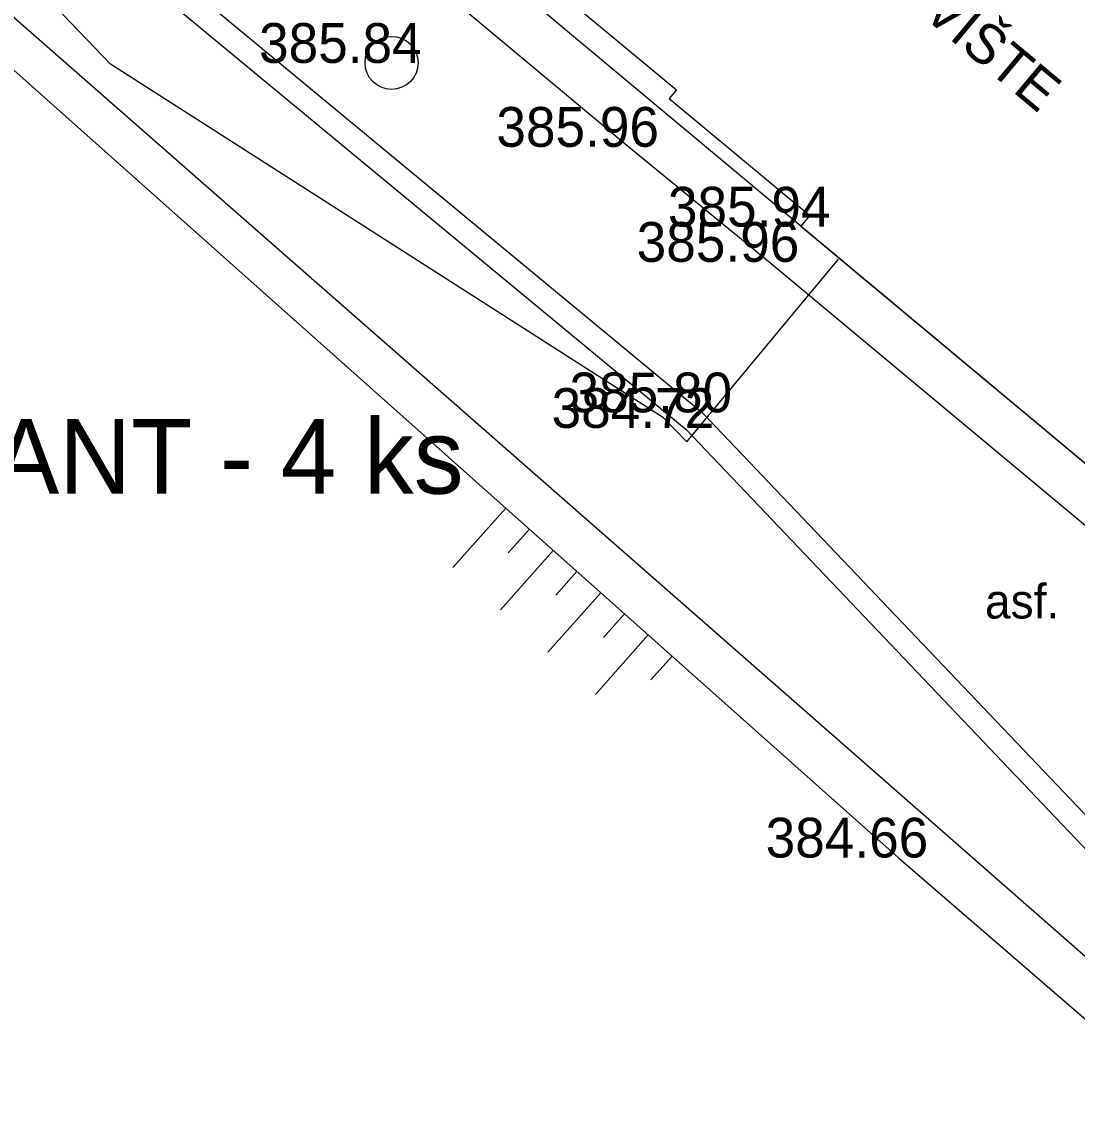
# Model space of a CAD drawing. Extents: x -438233 to -437334, y -1133133 to -1132623.
# Drawn here: x -438124.22 to -438104.32, y -1133015.76 to -1132995.04 of the extents above; entities that cross this region are included whole.
import ezdxf

# ---------------------------------------------------------------- set-up
doc = ezdxf.new("R2010")
doc.units = 0
for name, color, linetype in [('Vrstva 1', 7, 'Continuous'), ('Vrstva 10', 7, 'Continuous'), ('Vrstva 11', 7, 'Continuous'), ('Vrstva 14', 7, 'Continuous'), ('Vrstva 15', 7, 'Continuous'), ('Vrstva 27', 7, 'Continuous'), ('Vrstva 3', 7, 'Continuous'), ('Vrstva 40', 7, 'Continuous'), ('Vrstva 5', 7, 'Continuous'), ('Vrstva 53', 7, 'Continuous'), ('Vrstva 55', 7, 'Continuous'), ('Vrstva 58', 7, 'Continuous')]:
    doc.layers.add(name, color=color, linetype=linetype)

msp = doc.modelspace()

# ---------------------------------------------------------------- linework, layer by layer
at = {"layer": 'Vrstva 1'}
for p, q in [((-438117.25, -1132995.807), (-438117.25, -1132995.807)), ((-438112.774, -1132997.389), (-438112.774, -1132997.389)), ((-438109.538, -1132998.894), (-438109.538, -1132998.894)), ((-438110.127, -1132999.558), (-438110.127, -1132999.558)), ((-438111.395, -1133002.396), (-438111.395, -1133002.396)), ((-438111.732, -1133002.689), (-438111.732, -1133002.689)), ((-438107.695, -1133010.79), (-438107.695, -1133010.79))]:
    msp.add_line(p, q, dxfattribs=at)
at = {"layer": 'Vrstva 10'}
msp.add_lwpolyline([(-438136.916, -1132976.04), (-438130.815, -1132968.777), (-438110.909, -1132985.383), (-438109.206, -1132983.342), (-438101.698, -1132989.616), (-438102.771, -1132990.9), (-438091.189, -1133000.578), (-438097.908, -1133008.583)], close=True, dxfattribs=at)
at = {"layer": 'Vrstva 11'}
for points in [[(-438138.792, -1132977.357), (-438140.226, -1132979.081), (-438130.239, -1132987.383), (-438111.696, -1133002.719), (-438101.614, -1133013.302)], [(-438138.453, -1132977.639), (-438139.605, -1132979.024), (-438129.958, -1132987.044), (-438111.395, -1133002.396), (-438101.295, -1133012.998)], [(-438128.485, -1132984.283), (-438112.774, -1132997.389), (-438110.127, -1132999.558), (-438098.962, -1133008.857)]]:
    msp.add_lwpolyline(points, dxfattribs=at)
at = {"layer": 'Vrstva 14'}
msp.add_lwpolyline([(-438140.54, -1132981.557), (-438107.695, -1133010.79), (-438101.937, -1133015.758)], dxfattribs=at)
at = {"layer": 'Vrstva 15'}
for p, q in [((-438115.098, -1133004.201), (-438116.095, -1133005.321)), ((-438114.65, -1133004.6), (-438115.049, -1133005.048)), ((-438114.202, -1133004.999), (-438115.199, -1133006.119)), ((-438113.754, -1133005.398), (-438114.152, -1133005.846)), ((-438113.305, -1133005.797), (-438114.303, -1133006.917)), ((-438112.857, -1133006.195), (-438113.256, -1133006.644)), ((-438112.409, -1133006.594), (-438113.406, -1133007.715)), ((-438111.961, -1133006.993), (-438112.36, -1133007.441))]:
    msp.add_line(p, q, dxfattribs=at)
at = {"layer": 'Vrstva 27'}
msp.add_circle((-438117.25, -1132995.807), 0.5, dxfattribs=at)
at = {"layer": 'Vrstva 5'}
for p, q in [((-438116.463, -1132992.491), (-438111.878, -1132996.316)), ((-438111.878, -1132996.316), (-438112.013, -1132996.477)), ((-438112.013, -1132996.477), (-438109.364, -1132998.687)), ((-438109.364, -1132998.687), (-438109.538, -1132998.894)), ((-438109.531, -1132998.886), (-438097.908, -1133008.583))]:
    msp.add_line(p, q, dxfattribs=at)
at = {"layer": 'Vrstva 53'}
msp.add_line((-438111.68, -1133002.95), (-438108.82, -1132999.51), dxfattribs=at)
msp.add_lwpolyline([(-438111.68, -1133002.95), (-438112.12, -1133002.5), (-438122.55, -1132995.83), (-438124.94, -1132993.34), (-438127.48, -1132990.73), (-438128.12, -1132989.43), (-438134.1, -1132984.54), (-438140.26, -1132979.82), (-438141.19, -1132978.73), (-438141.97, -1132973.72), (-438142.51, -1132968.08), (-438140.08, -1132963.83), (-438137.6, -1132962.74), (-438135.49, -1132962.32), (-438133.71, -1132961.01), (-438132.67, -1132959.55), (-438131.52, -1132960.06), (-438130.71, -1132960.47)], dxfattribs=at)
at = {"layer": 'Vrstva 58'}
msp.add_lwpolyline([(-438130.562, -1132992.413), (-438128.998, -1132990.895), (-438101.316, -1133015.148), (-438080.005, -1133005.995)], dxfattribs=at)

# ---------------------------------------------------------------- texts
at = {"layer": 'Vrstva 1'}
msp.add_text('ACER CAMPESTRE ELEGANT - 4 ks', height=1.40625, dxfattribs=at).set_placement((-438147.762, -1133003.93))
at = {"layer": 'Vrstva 3'}
for s, p in [('385.84 ', (-438119.75, -1132995.807)), ('385.96 ', (-438115.274, -1132997.389)), ('385.94 ', (-438112.038, -1132998.894)), ('385.96 ', (-438112.627, -1132999.558)), ('385.80 ', (-438113.895, -1133002.396)), ('384.72 ', (-438114.232, -1133002.689)), ('384.66 ', (-438110.195, -1133010.79))]:
    msp.add_text(s, height=0.75, dxfattribs=at).set_placement(p)
at = {"layer": 'Vrstva 40'}
msp.add_text('asf.', height=0.65, dxfattribs=at).set_placement((-438106.058, -1133006.283))
at = {"layer": 'Vrstva 55'}
msp.add_text('AUTOBUSOVÉ STANOVIŠTE', height=0.74999, rotation=320.1027, dxfattribs=at).set_placement((-438115.474, -1132988.046))
msp.add_text('AUTOBUSOVÉ STANOVIŠTE', height=0.74999, rotation=320.1027, dxfattribs=at).set_placement((-438115.474, -1132988.046))

doc.saveas('drawing.dxf')
